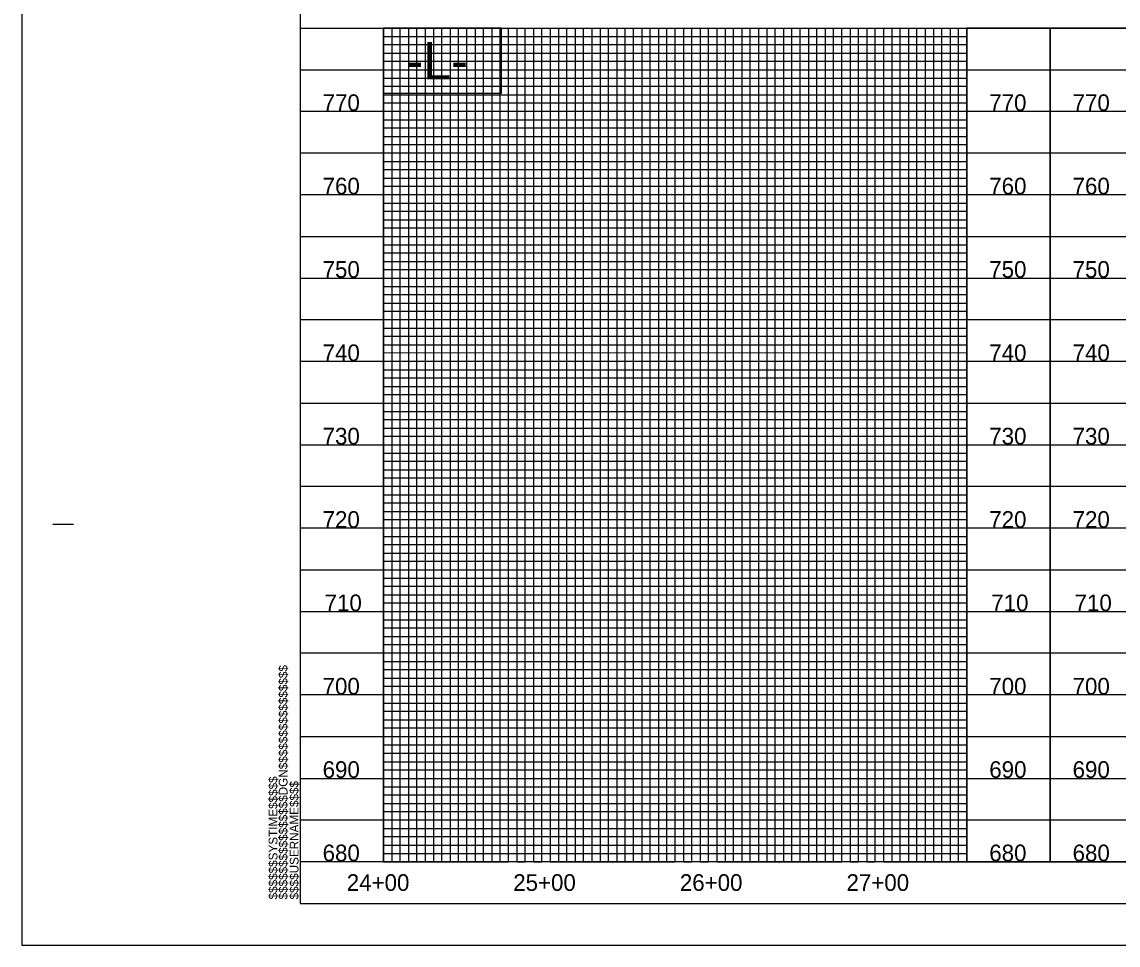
# Model space of a CAD drawing. Extents: x 1524869 to 1526553, y 501099 to 502199.
# Drawn here: x 1524869 to 1525527, y 501099 to 501652 of the extents above; entities that cross this region are included whole.
import ezdxf

# ---------------------------------------------------------------- set-up
doc = ezdxf.new("R2010")
doc.units = 0
for name, color, linetype in [('Exist Vertical Profile Horizontal Axis Label Major', 7, 'Continuous'), ('Exist Vertical Profile Vertical Axis Label', 7, 'Continuous'), ('Prop Grid Mask', 7, 'Continuous'), ('Prop Horizontal Alignment Curve and Spiral Data', 7, 'Continuous'), ('Sheet Layout Profile Border Port 2', 7, 'Continuous'), ('Sheet Plot Border Outside CELL', 7, 'Continuous'), ('Sheet Profile CELL', 7, 'Continuous'), ('Sheet Profile Grid Major CELL', 7, 'Continuous'), ('Sheet Profile Grid Middle CELL', 7, 'Continuous'), ('Sheet Profile Grid Minor CELL', 7, 'Continuous')]:
    doc.layers.add(name, color=color, linetype=linetype)

msp = doc.modelspace()

# ---------------------------------------------------------------- linework, layer by layer
at = {"layer": 'Prop Grid Mask'}
msp.add_lwpolyline([(1525086.08, 501609.52), (1525156.81, 501609.52), (1525156.81, 501648.56), (1525086.08, 501648.56)], close=True, dxfattribs=at)
at = {"layer": 'Sheet Layout Profile Border Port 2'}
msp.add_lwpolyline([(1525086.08, 501648.56), (1525436.08, 501648.56), (1525436.08, 501148.56), (1525086.08, 501148.56)], close=True, dxfattribs=at)
at = {"layer": 'Sheet Plot Border Outside CELL'}
msp.add_lwpolyline([(1524869.08, 501098.56), (1526553.08, 501098.56), (1526553.08, 502198.56), (1524869.08, 502198.56)], close=True, dxfattribs=at)
at = {"layer": 'Sheet Profile CELL'}
for p, q in [((1525036.08, 501648.56), (1526536.08, 501648.56)), ((1524887.58, 501351.06), (1524900.08, 501351.06)), ((1526536.08, 501148.56), (1525036.08, 501148.56)), ((1525036.08, 501123.56), (1526536.08, 501123.56)), ((1525036.08, 501123.56), (1525036.08, 501123.56)), ((1525036.08, 501123.56), (1525036.08, 501123.56)), ((1525036.08, 501123.56), (1525036.08, 501123.56)), ((1525036.08, 501123.56), (1525036.08, 501123.56)), ((1525036.08, 501123.56), (1525036.08, 501123.56)), ((1525036.08, 501123.56), (1525036.08, 501123.56)), ((1525036.08, 501123.56), (1525036.08, 501123.56))]:
    msp.add_line(p, q, dxfattribs=at)
for points in [[(1526536.08, 502173.56), (1525036.08, 502173.56), (1525036.08, 501123.56), (1526536.08, 501123.56)], [(1525436.08, 501148.56), (1525486.08, 501148.56), (1525486.08, 501648.56), (1525436.08, 501648.56)], [(1525486.08, 501148.56), (1525536.08, 501148.56), (1525536.08, 501648.56), (1525486.08, 501648.56)]]:
    msp.add_lwpolyline(points, close=True, dxfattribs=at)
msp.add_lwpolyline([(1525073.58, 501123.56), (1525073.58, 501123.56)], dxfattribs=at)
at = {"layer": 'Sheet Profile Grid Major CELL'}
msp.add_line((1525036.08, 501148.56), (1525036.08, 501148.56), dxfattribs=at)
for points in [[(1525086.08, 501648.56), (1525086.08, 501148.56), (1525136.08, 501148.56), (1525136.08, 501648.56), (1525186.08, 501648.56), (1525186.08, 501148.56), (1525236.08, 501148.56), (1525236.08, 501648.56), (1525286.08, 501648.56), (1525286.08, 501148.56), (1525336.08, 501148.56), (1525336.08, 501648.56), (1525386.08, 501648.56), (1525386.08, 501148.56), (1525436.08, 501148.56), (1525436.08, 501648.56), (1525486.08, 501648.56), (1525486.08, 501148.56), (1525536.08, 501148.56)], [(1526536.08, 501598.56), (1525036.08, 501598.56)], [(1526536.08, 501548.56), (1525036.08, 501548.56), (1525036.08, 501498.56), (1526536.08, 501498.56)], [(1526536.08, 501448.56), (1525036.08, 501448.56), (1525036.08, 501398.56), (1526536.08, 501398.56)], [(1526536.08, 501348.56), (1525036.08, 501348.56), (1525036.08, 501298.56), (1526536.08, 501298.56)], [(1526536.08, 501248.56), (1525036.08, 501248.56), (1525036.08, 501248.56), (1525036.08, 501198.56), (1526536.08, 501198.56)], [(1526536.08, 501148.56), (1525036.08, 501148.56)]]:
    msp.add_lwpolyline(points, dxfattribs=at)
at = {"layer": 'Sheet Profile Grid Middle CELL'}
for points in [[(1525061.08, 501648.56), (1525111.08, 501648.56), (1525111.08, 501148.56), (1525161.08, 501148.56), (1525161.08, 501648.56), (1525211.08, 501648.56), (1525211.08, 501148.56), (1525261.08, 501148.56), (1525261.08, 501648.56), (1525311.08, 501648.56), (1525311.08, 501148.56), (1525361.08, 501148.56), (1525361.08, 501648.56), (1525411.08, 501648.56), (1525411.08, 501148.56)], [(1525036.08, 501623.56), (1526536.08, 501623.56)], [(1526536.08, 501573.56), (1525036.08, 501573.56), (1525036.08, 501523.56), (1526536.08, 501523.56)], [(1526536.08, 501473.56), (1525036.08, 501473.56), (1525036.08, 501423.56), (1526536.08, 501423.56)], [(1526536.08, 501373.56), (1525036.08, 501373.56), (1525036.08, 501323.56), (1526536.08, 501323.56)], [(1526536.08, 501273.56), (1525036.08, 501273.56), (1525036.08, 501223.56), (1526536.08, 501223.56)], [(1526536.08, 501173.56), (1525036.08, 501173.56)]]:
    msp.add_lwpolyline(points, dxfattribs=at)
at = {"layer": 'Sheet Profile Grid Minor CELL'}
for p, q in [((1525086.08, 501643.56), (1525436.08, 501643.56)), ((1525436.08, 501638.56), (1525086.08, 501638.56)), ((1525086.08, 501633.56), (1525436.08, 501633.56)), ((1525436.08, 501628.56), (1525086.08, 501628.56)), ((1525086.08, 501618.56), (1525436.08, 501618.56)), ((1525436.08, 501613.56), (1525086.08, 501613.56)), ((1525086.08, 501608.56), (1525436.08, 501608.56)), ((1525436.08, 501603.56), (1525086.08, 501603.56)), ((1525086.08, 501593.56), (1525436.08, 501593.56)), ((1525436.08, 501588.56), (1525086.08, 501588.56)), ((1525086.08, 501583.56), (1525436.08, 501583.56)), ((1525436.08, 501578.56), (1525086.08, 501578.56)), ((1525086.08, 501568.56), (1525436.08, 501568.56)), ((1525436.08, 501563.56), (1525086.08, 501563.56)), ((1525086.08, 501558.56), (1525436.08, 501558.56)), ((1525436.08, 501553.56), (1525086.08, 501553.56)), ((1525086.08, 501543.56), (1525436.08, 501543.56)), ((1525436.08, 501538.56), (1525086.08, 501538.56)), ((1525086.08, 501533.56), (1525436.08, 501533.56)), ((1525436.08, 501528.56), (1525086.08, 501528.56)), ((1525086.08, 501518.56), (1525436.08, 501518.56)), ((1525436.08, 501513.56), (1525086.08, 501513.56)), ((1525086.08, 501508.56), (1525436.08, 501508.56)), ((1525436.08, 501503.56), (1525086.08, 501503.56)), ((1525086.08, 501493.56), (1525436.08, 501493.56)), ((1525436.08, 501488.56), (1525086.08, 501488.56)), ((1525086.08, 501483.56), (1525436.08, 501483.56)), ((1525436.08, 501478.56), (1525086.08, 501478.56)), ((1525086.08, 501468.56), (1525436.08, 501468.56)), ((1525436.08, 501463.56), (1525086.08, 501463.56)), ((1525086.08, 501458.56), (1525436.08, 501458.56)), ((1525436.08, 501453.67), (1525086.08, 501453.71)), ((1525086.08, 501443.56), (1525436.08, 501443.56)), ((1525436.08, 501438.56), (1525086.08, 501438.56)), ((1525086.08, 501433.56), (1525436.08, 501433.56)), ((1525436.08, 501428.56), (1525086.08, 501428.56)), ((1525086.08, 501418.56), (1525436.08, 501418.56)), ((1525436.08, 501413.56), (1525086.08, 501413.56)), ((1525086.08, 501408.56), (1525436.08, 501408.56)), ((1525436.08, 501403.56), (1525086.08, 501403.56)), ((1525086.08, 501393.56), (1525436.08, 501393.56)), ((1525436.08, 501388.56), (1525086.08, 501388.56)), ((1525086.08, 501383.56), (1525436.08, 501383.56)), ((1525436.08, 501378.56), (1525086.08, 501378.56)), ((1525086.08, 501368.56), (1525436.08, 501368.56)), ((1525436.08, 501363.56), (1525086.08, 501363.56)), ((1525086.08, 501358.56), (1525436.08, 501358.56)), ((1525436.08, 501353.56), (1525086.08, 501353.56)), ((1525086.08, 501343.56), (1525436.08, 501343.56)), ((1525436.08, 501338.56), (1525086.08, 501338.56)), ((1525086.08, 501333.56), (1525436.08, 501333.56)), ((1525436.08, 501328.56), (1525086.08, 501328.56)), ((1525086.08, 501318.56), (1525436.08, 501318.56)), ((1525436.08, 501313.56), (1525086.08, 501313.56)), ((1525086.08, 501308.56), (1525436.08, 501308.56)), ((1525436.08, 501303.56), (1525086.08, 501303.56)), ((1525086.08, 501293.56), (1525436.08, 501293.56)), ((1525436.08, 501288.56), (1525086.08, 501288.56)), ((1525086.08, 501283.56), (1525436.08, 501283.56)), ((1525436.08, 501278.56), (1525086.08, 501278.56)), ((1525086.08, 501268.56), (1525436.08, 501268.56)), ((1525436.08, 501263.56), (1525086.08, 501263.56)), ((1525086.08, 501258.56), (1525436.08, 501258.56)), ((1525436.08, 501253.56), (1525086.08, 501253.56)), ((1525086.08, 501243.56), (1525436.08, 501243.56)), ((1525436.08, 501238.56), (1525086.08, 501238.56)), ((1525086.08, 501233.56), (1525436.08, 501233.56)), ((1525436.08, 501228.56), (1525086.08, 501228.56)), ((1525086.08, 501218.56), (1525436.08, 501218.56)), ((1525436.08, 501213.56), (1525086.08, 501213.56)), ((1525086.08, 501208.56), (1525436.08, 501208.56)), ((1525436.08, 501203.56), (1525086.08, 501203.56)), ((1525086.08, 501193.56), (1525436.08, 501193.56)), ((1525436.08, 501188.56), (1525086.08, 501188.56)), ((1525086.08, 501183.56), (1525436.08, 501183.56)), ((1525436.08, 501178.56), (1525086.08, 501178.56)), ((1525086.08, 501168.56), (1525436.08, 501168.56)), ((1525436.08, 501163.56), (1525086.08, 501163.56)), ((1525086.08, 501158.56), (1525436.08, 501158.56)), ((1525086.08, 501153.56), (1525436.08, 501153.56))]:
    msp.add_line(p, q, dxfattribs=at)
for points in [[(1525086.08, 501648.56), (1525091.08, 501648.56), (1525091.08, 501148.56), (1525096.08, 501148.56), (1525096.08, 501648.56), (1525101.08, 501648.56), (1525101.08, 501148.56), (1525106.08, 501148.56), (1525106.08, 501648.56), (1525116.08, 501648.56), (1525116.08, 501148.56), (1525121.08, 501148.56), (1525121.08, 501648.56), (1525126.08, 501648.56), (1525126.08, 501148.56), (1525131.08, 501148.56), (1525141.08, 501148.56), (1525146.08, 501148.56), (1525146.08, 501648.56), (1525151.08, 501648.56), (1525151.08, 501148.56), (1525156.08, 501148.56), (1525156.08, 501648.56), (1525166.08, 501648.56), (1525166.08, 501148.56), (1525171.08, 501148.56), (1525171.08, 501648.56), (1525176.08, 501648.56), (1525176.08, 501148.56), (1525181.08, 501148.56), (1525181.08, 501648.56), (1525191.08, 501648.56), (1525191.08, 501148.56), (1525196.08, 501148.56), (1525196.08, 501648.56), (1525201.08, 501648.56), (1525201.08, 501148.56), (1525206.08, 501148.56), (1525206.08, 501648.56), (1525216.08, 501648.56), (1525216.08, 501148.56), (1525221.08, 501148.56), (1525221.08, 501648.56), (1525226.08, 501648.56), (1525226.08, 501148.56), (1525231.08, 501148.56), (1525231.08, 501648.56), (1525241.08, 501648.56), (1525241.08, 501148.56), (1525246.08, 501148.56), (1525246.08, 501648.56), (1525251.08, 501648.56), (1525251.08, 501148.56), (1525256.08, 501148.56), (1525256.08, 501648.56), (1525266.08, 501648.56), (1525266.08, 501148.56), (1525271.08, 501148.56), (1525271.08, 501648.56), (1525276.08, 501648.56), (1525276.08, 501148.56), (1525281.08, 501148.56), (1525281.08, 501648.56), (1525291.08, 501648.56), (1525291.08, 501148.56), (1525296.08, 501148.56), (1525296.08, 501648.56), (1525301.08, 501648.56), (1525301.08, 501148.56)], [(1525131.08, 501148.56), (1525131.08, 501648.56), (1525141.08, 501648.56), (1525141.08, 501148.56)], [(1525301.08, 501148.56), (1525306.08, 501148.56), (1525306.08, 501648.56), (1525316.08, 501648.56), (1525316.08, 501148.56), (1525321.08, 501148.56), (1525321.08, 501648.56), (1525326.08, 501648.56), (1525326.08, 501148.56), (1525331.08, 501148.56), (1525331.08, 501648.56), (1525341.08, 501648.56), (1525341.08, 501148.56), (1525346.08, 501148.56), (1525346.08, 501648.56), (1525351.08, 501648.56), (1525351.08, 501148.56), (1525356.08, 501148.56), (1525356.08, 501648.56), (1525366.08, 501648.56), (1525366.08, 501148.56), (1525371.08, 501148.56), (1525371.08, 501648.56), (1525376.08, 501648.56), (1525376.08, 501148.56), (1525381.08, 501148.56), (1525381.08, 501648.56), (1525391.08, 501648.56), (1525391.08, 501148.56), (1525396.08, 501148.56), (1525396.08, 501648.56), (1525401.08, 501648.56), (1525401.08, 501148.56), (1525406.08, 501148.56), (1525406.08, 501648.56), (1525416.08, 501648.56), (1525416.08, 501148.56), (1525421.08, 501148.56), (1525421.08, 501648.56), (1525426.08, 501648.56), (1525426.08, 501148.56), (1525431.08, 501148.56), (1525431.08, 501648.56), (1525441.08, 501648.56)]]:
    msp.add_lwpolyline(points, dxfattribs=at)

# ---------------------------------------------------------------- texts
at = {"layer": 'Exist Vertical Profile Horizontal Axis Label Major'}
for s, p in [('24+00', (1525064.01, 501131.06)), ('25+00', (1525163.87, 501131.06)), ('26+00', (1525263.85, 501131.06)), ('27+00', (1525363.85, 501131.06))]:
    msp.add_text(s, height=10, dxfattribs=at).set_placement(p)
at = {"layer": 'Exist Vertical Profile Vertical Axis Label'}
for s, p in [('770', (1525049.51, 501598.81)), ('770', (1525449.51, 501598.81)), ('770', (1525499.51, 501598.81)), ('760', (1525049.51, 501548.81)), ('760', (1525449.51, 501548.81)), ('760', (1525499.51, 501548.81)), ('750', (1525049.51, 501498.81)), ('750', (1525449.51, 501498.81)), ('750', (1525499.51, 501498.81)), ('740', (1525049.51, 501448.81)), ('740', (1525449.51, 501448.81)), ('740', (1525499.51, 501448.81)), ('730', (1525049.51, 501398.81)), ('730', (1525449.51, 501398.81)), ('730', (1525499.51, 501398.81)), ('720', (1525049.51, 501348.81)), ('720', (1525449.51, 501348.81)), ('720', (1525499.51, 501348.81)), ('710', (1525050.71, 501298.81)), ('710', (1525450.71, 501298.81)), ('710', (1525500.71, 501298.81)), ('700', (1525049.51, 501248.81)), ('700', (1525449.51, 501248.81)), ('700', (1525499.51, 501248.81)), ('690', (1525049.51, 501198.81)), ('690', (1525449.51, 501198.81)), ('690', (1525499.51, 501198.81)), ('680', (1525049.51, 501148.81)), ('680', (1525449.51, 501148.81)), ('680', (1525499.51, 501148.81))]:
    msp.add_text(s, height=10, dxfattribs=at).set_placement(p)
at = {"layer": 'Prop Horizontal Alignment Curve and Spiral Data'}
msp.add_text('-L-', height=22.5, rotation=360, dxfattribs=at).set_placement((1525099.8, 501617.79))
at = {"layer": 'Sheet Profile CELL'}
for s, p in [('$$$$$$$$$$$$$$$$DGN$$$$$$$$$$$$$$$$', (1525028.44, 501125.94)), ('$$$$$$SYSTIME$$$$$', (1525022.39, 501125.94)), ('$$$$USERNAME$$$$', (1525035.02, 501125.95))]:
    msp.add_text(s, height=5.25, rotation=90, dxfattribs=at).set_placement(p)

doc.saveas('drawing.dxf')
